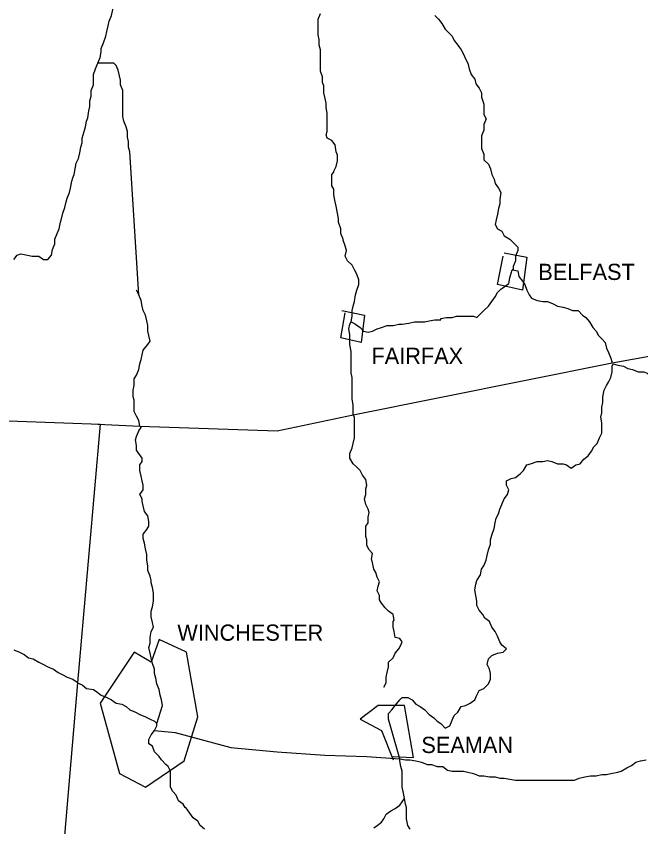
# Model space of a CAD drawing. Extents: x 0 to 34, y 0 to 22.
# Drawn here: x 3.569 to 4.319, y 17.195 to 18.17 of the extents above; entities that cross this region are included whole.
import ezdxf

# ---------------------------------------------------------------- set-up
doc = ezdxf.new("R2010")
doc.units = 0
doc.layers.add('Default', color=7, linetype='Continuous')

msp = doc.modelspace()

# ---------------------------------------------------------------- linework, layer by layer
at = {"layer": 'Default'}
for points in [[(3.00408, 18.71557), (2.98363, 18.02022), (2.9659, 17.693), (3.31221, 17.68346), (3.514, 17.68482), (3.6258, 17.68073), (3.66943, 17.67937)], [(3.6667, 18.11293), (3.66943, 18.11975), (3.67079, 18.12657), (3.67079, 18.13066), (3.67352, 18.13747), (3.67625, 18.14566), (3.67761, 18.15111), (3.67897, 18.15793), (3.68034, 18.16338), (3.68306, 18.1702), (3.68443, 18.17565), (3.68579, 18.18247), (3.68579, 18.18792)], [(3.94211, 18.04613), (3.94211, 18.05294), (3.94075, 18.05976), (3.94075, 18.06521), (3.93939, 18.07203), (3.93802, 18.07748), (3.93802, 18.08566), (3.93666, 18.08976), (3.93666, 18.09657), (3.93393, 18.10339), (3.93393, 18.11021), (3.93393, 18.11566), (3.93393, 18.12111), (3.93393, 18.12929), (3.93257, 18.13475), (3.93257, 18.14157), (3.93121, 18.14702), (3.93121, 18.15384), (3.93121, 18.16065), (3.93121, 18.16611), (3.93393, 18.17292)], [(4.07164, 18.1702), (4.07573, 18.16611), (4.07982, 18.16065), (4.08391, 18.15384), (4.088, 18.14975), (4.09209, 18.14566), (4.09482, 18.1402), (4.09891, 18.13475), (4.103, 18.12929), (4.10572, 18.12384), (4.10845, 18.11839), (4.11118, 18.11293), (4.11254, 18.10612), (4.11527, 18.0993), (4.11936, 18.09385), (4.12072, 18.08839), (4.12481, 18.08294), (4.12754, 18.07748), (4.12754, 18.07203), (4.13027, 18.06385), (4.13027, 18.05703), (4.13027, 18.05158), (4.13299, 18.04613), (4.13027, 18.03931), (4.13027, 18.03249), (4.12754, 18.02567), (4.12754, 18.02295), (4.12754, 18.02158)], [(3.63807, 17.97932), (3.63943, 17.98614), (3.6408, 17.99295), (3.64352, 17.99841), (3.64489, 18.00522), (3.64625, 18.01204), (3.64762, 18.01749), (3.64762, 18.02295), (3.65034, 18.03113), (3.65171, 18.03658), (3.65307, 18.0434), (3.65443, 18.04749), (3.6558, 18.05567), (3.65716, 18.06112), (3.65716, 18.06794), (3.65852, 18.07339), (3.65852, 18.08021), (3.66125, 18.08703), (3.66125, 18.09385), (3.66125, 18.0993), (3.66398, 18.10612), (3.66534, 18.11021), (3.6667, 18.11293)], [(3.70488, 18.00659), (3.70352, 18.01204), (3.70352, 18.01886), (3.70215, 18.02431), (3.70215, 18.03113), (3.70079, 18.03658), (3.69806, 18.0434), (3.6967, 18.04885), (3.6967, 18.05567), (3.6967, 18.06112), (3.6967, 18.06794), (3.6967, 18.07476), (3.6967, 18.08021), (3.69397, 18.08703), (3.69397, 18.09248), (3.69261, 18.09794), (3.69124, 18.10475), (3.68852, 18.11021), (3.68579, 18.11293), (3.67897, 18.11293), (3.67216, 18.11293), (3.6667, 18.11293)], [(3.95029, 17.98341), (3.95302, 17.98886), (3.95438, 17.99568), (3.95438, 18.0025), (3.95302, 18.00659), (3.95166, 18.01477), (3.94757, 18.02022), (3.94211, 18.02295), (3.94075, 18.02704), (3.94211, 18.03113), (3.94211, 18.03795), (3.94211, 18.04476), (3.94211, 18.04476), (3.94211, 18.04613)], [(4.12754, 18.02158), (4.12754, 18.01477), (4.12754, 18.01068), (4.13027, 18.00386), (4.13027, 17.99704), (4.13572, 17.99159), (4.13845, 17.98614), (4.13981, 17.97932), (4.14254, 17.97386), (4.1439, 17.96841), (4.14799, 17.96296), (4.15072, 17.9575), (4.14935, 17.94932), (4.14935, 17.94387), (4.14799, 17.93842), (4.14663, 17.9316), (4.14526, 17.92478), (4.1439, 17.91933), (4.14663, 17.91387), (4.15208, 17.91115), (4.15481, 17.90569), (4.16162, 17.9016), (4.16572, 17.89751), (4.17117, 17.89206), (4.17117, 17.88797), (4.16844, 17.88115), (4.16844, 17.8757), (4.16572, 17.86888), (4.16572, 17.86479), (4.16435, 17.86479)], [(3.71579, 17.8348), (3.70488, 18.00659)], [(3.9612, 17.9016), (3.95848, 17.90842), (3.95848, 17.91387), (3.95575, 17.92205), (3.95575, 17.92614), (3.95438, 17.93296), (3.95302, 17.94114), (3.95166, 17.9466), (3.95029, 17.95478), (3.95029, 17.96159), (3.94757, 17.96568), (3.94757, 17.97386), (3.94757, 17.97932), (3.95029, 17.98204), (3.95029, 17.98341)], [(3.56581, 17.87706), (3.5699, 17.88252), (3.57399, 17.88388), (3.58217, 17.88252), (3.58762, 17.88115), (3.59581, 17.88115), (3.60126, 17.87706), (3.60671, 17.87706), (3.6108, 17.88252), (3.61217, 17.88933), (3.61489, 17.89615), (3.61489, 17.9016), (3.61762, 17.90842), (3.62035, 17.91387), (3.62171, 17.92205), (3.62307, 17.92614), (3.62444, 17.93296), (3.62716, 17.93978), (3.62853, 17.9466), (3.62989, 17.95069), (3.63262, 17.9575), (3.63398, 17.96296), (3.63534, 17.97114), (3.63671, 17.97523), (3.63807, 17.97932), (3.63807, 17.97932)], [(3.97075, 17.80207), (3.97211, 17.80889), (3.97211, 17.81571), (3.97347, 17.82116), (3.97484, 17.82661), (3.9762, 17.8348), (3.97756, 17.84025), (3.98029, 17.84707), (3.98029, 17.85252), (3.97756, 17.85934), (3.97484, 17.86479), (3.97211, 17.87024), (3.96666, 17.8757), (3.96393, 17.88115), (3.96529, 17.88797), (3.96393, 17.89342), (3.9612, 17.90024), (3.9612, 17.9016), (3.9612, 17.9016)], [(4.15481, 17.88524), (4.18208, 17.87979), (4.17662, 17.84025), (4.14663, 17.84707), (4.15344, 17.88115)], [(4.07846, 17.80616), (4.08527, 17.80753), (4.09209, 17.80753), (4.09754, 17.80889), (4.103, 17.80889), (4.11118, 17.80889), (4.118, 17.80889), (4.12209, 17.80753), (4.12754, 17.81298), (4.13027, 17.81571), (4.13572, 17.82116), (4.13981, 17.82661), (4.1439, 17.83207), (4.14663, 17.83752), (4.15072, 17.84161), (4.15481, 17.84434), (4.16026, 17.84843), (4.16162, 17.85525), (4.16299, 17.8607), (4.16435, 17.86479)], [(4.16435, 17.86479), (4.17117, 17.86343), (4.17253, 17.85661), (4.17662, 17.85116), (4.17935, 17.84707), (4.18208, 17.84025), (4.1848, 17.8348), (4.18753, 17.83071), (4.19435, 17.82798), (4.20116, 17.82661), (4.20662, 17.82661), (4.21343, 17.82389), (4.21889, 17.82116), (4.22571, 17.8198), (4.23116, 17.81843), (4.23661, 17.81571), (4.24343, 17.81571), (4.24888, 17.81025), (4.25297, 17.80753), (4.25706, 17.80207), (4.26115, 17.79526), (4.26524, 17.79117), (4.26797, 17.78571), (4.27206, 17.78162), (4.27615, 17.77753), (4.27752, 17.77071), (4.28024, 17.76526), (4.28297, 17.75844), (4.28433, 17.75299)], [(3.71715, 17.67664), (3.71579, 17.68346), (3.71306, 17.68891), (3.71033, 17.69436), (3.71033, 17.70118), (3.71033, 17.708), (3.70897, 17.71209), (3.70897, 17.72027), (3.71033, 17.72572), (3.71033, 17.7339), (3.71306, 17.73799), (3.71579, 17.74481), (3.71715, 17.75163), (3.71851, 17.75708), (3.71988, 17.76253), (3.72124, 17.76799), (3.72669, 17.7748), (3.72942, 17.7789), (3.72806, 17.78571), (3.72669, 17.79117), (3.72669, 17.79798), (3.72533, 17.80344), (3.72397, 17.81025), (3.72124, 17.81571), (3.71988, 17.82116), (3.71851, 17.82798), (3.71579, 17.8348), (3.71306, 17.84025), (3.71306, 17.84025)], [(3.6667, 17.67937), (3.71715, 17.67664), (3.88212, 17.67118), (3.97347, 17.69027), (4.28433, 17.75299), (4.662, 17.82116), (4.68245, 17.82661)], [(3.95984, 17.81571), (3.98711, 17.81025), (3.98302, 17.77753), (3.95848, 17.78299), (3.96393, 17.81298)], [(3.97347, 17.69027), (3.97347, 17.69709), (3.97347, 17.70254), (3.97211, 17.70936), (3.97211, 17.71618), (3.97211, 17.72163), (3.97211, 17.72845), (3.97211, 17.73527), (3.97075, 17.74072), (3.97075, 17.74754), (3.97075, 17.75435), (3.97075, 17.76117), (3.97075, 17.76662), (3.96938, 17.7748), (3.96938, 17.78026), (3.96938, 17.78708), (3.96802, 17.79389), (3.96938, 17.79935), (3.97075, 17.80207)], [(3.97075, 17.80207), (3.9762, 17.79935), (3.98165, 17.79526), (3.98574, 17.79117), (3.9912, 17.7898), (3.99665, 17.79117), (4.0021, 17.79389), (4.00756, 17.79526), (4.01438, 17.79798), (4.02119, 17.79798), (4.02801, 17.79935), (4.0321, 17.79935), (4.04028, 17.80071), (4.0471, 17.80207), (4.05255, 17.80207), (4.05937, 17.80207), (4.06482, 17.80344), (4.07164, 17.8048), (4.07846, 17.8048), (4.07846, 17.80616)], [(4.15753, 17.40941), (4.15208, 17.4135), (4.14935, 17.41759), (4.14663, 17.42441), (4.1439, 17.42986), (4.13981, 17.43531), (4.13708, 17.44213), (4.13163, 17.44622), (4.1289, 17.45031), (4.12481, 17.45576), (4.12209, 17.46122), (4.12209, 17.46667), (4.12072, 17.47349), (4.11936, 17.48031), (4.12072, 17.48712), (4.12209, 17.49121), (4.12618, 17.49803), (4.12754, 17.50485), (4.13027, 17.50894), (4.13299, 17.51575), (4.13436, 17.52121), (4.13572, 17.52803), (4.13845, 17.53484), (4.13845, 17.5403), (4.13981, 17.54575), (4.14254, 17.55393), (4.1439, 17.56075), (4.14526, 17.5662), (4.14799, 17.57166), (4.14935, 17.57711), (4.15208, 17.58256), (4.15481, 17.58938), (4.1589, 17.59483), (4.16026, 17.60029), (4.15753, 17.60574), (4.15753, 17.61119), (4.16299, 17.61392), (4.16844, 17.61528), (4.1739, 17.61937), (4.17799, 17.62347), (4.18208, 17.63028), (4.18617, 17.63165), (4.19435, 17.63437), (4.20116, 17.63437), (4.20662, 17.63574), (4.21207, 17.63437), (4.21889, 17.63165), (4.22571, 17.63165), (4.2298, 17.63028), (4.23525, 17.62619), (4.2407, 17.63028), (4.24616, 17.63165), (4.25025, 17.6371), (4.2557, 17.64119), (4.25979, 17.64664), (4.26252, 17.6521), (4.26661, 17.65619), (4.26934, 17.663), (4.27206, 17.66846), (4.27206, 17.67528), (4.27206, 17.68073), (4.2707, 17.68755), (4.27206, 17.693), (4.27206, 17.69982), (4.27343, 17.70527), (4.27343, 17.71209), (4.27479, 17.72027), (4.27752, 17.72572), (4.28024, 17.72981), (4.28297, 17.73527), (4.28433, 17.74208), (4.28433, 17.7489), (4.2857, 17.75163)], [(4.2857, 17.75163), (4.29115, 17.75026), (4.29797, 17.7489), (4.30342, 17.74617), (4.30887, 17.74481), (4.31569, 17.74208), (4.32251, 17.74208), (4.3266, 17.74072), (4.33205, 17.73527), (4.33478, 17.72981), (4.34023, 17.72709), (4.34569, 17.72299), (4.35114, 17.72027), (4.35523, 17.71618), (4.35796, 17.71618)], [(3.98983, 17.60574), (3.98847, 17.61256), (3.98438, 17.61801), (3.98165, 17.62347), (3.97756, 17.62756), (3.97347, 17.63165), (3.96938, 17.63846), (3.96938, 17.64392), (3.97211, 17.65073), (3.97347, 17.65619), (3.97484, 17.663), (3.97484, 17.66846), (3.97484, 17.67528), (3.97484, 17.68073), (3.97484, 17.68755), (3.97347, 17.69027)], [(3.66943, 17.67937), (3.64216, 17.36851), (3.58899, 16.7427), (3.54127, 16.15506), (3.53172, 15.98191), (3.53036, 15.95873)], [(3.71988, 17.58938), (3.71715, 17.59483), (3.72124, 17.60029), (3.72124, 17.60574), (3.71988, 17.61119), (3.71851, 17.61665), (3.71715, 17.62347), (3.71715, 17.63028), (3.71988, 17.63437), (3.71988, 17.63846), (3.71579, 17.64392), (3.71306, 17.64801), (3.71306, 17.65346), (3.7117, 17.66028), (3.71306, 17.66437), (3.71579, 17.67118), (3.71851, 17.67528), (3.71715, 17.67664), (3.71715, 17.67664)], [(4.02256, 17.44349), (4.02119, 17.45031), (4.01574, 17.4544), (4.01165, 17.45849), (4.00756, 17.46394), (4.00483, 17.46804), (4.00483, 17.47349), (4.0021, 17.47894), (4.00347, 17.4844), (4.00483, 17.48985), (4.0021, 17.4953), (4.00074, 17.50076), (3.99801, 17.50485), (3.99665, 17.51303), (3.99529, 17.51712), (3.99665, 17.52394), (3.99256, 17.52803), (3.98983, 17.53348), (3.98983, 17.5403), (3.98847, 17.54439), (3.98847, 17.54984), (3.98847, 17.55666), (3.9912, 17.56075), (3.9912, 17.56756), (3.99256, 17.57302), (3.9912, 17.57711), (3.98847, 17.58256), (3.98711, 17.58938), (3.98847, 17.59483), (3.98847, 17.60165), (3.98983, 17.60574), (3.98983, 17.60574), (3.98983, 17.60574)], [(3.73078, 17.49121), (3.72942, 17.49667), (3.72669, 17.50348), (3.72669, 17.50894), (3.72533, 17.51575), (3.72533, 17.52257), (3.72397, 17.52939), (3.7226, 17.53621), (3.72124, 17.54166), (3.72124, 17.54711), (3.72533, 17.55257), (3.72806, 17.55666), (3.72806, 17.56211), (3.72669, 17.56893), (3.7226, 17.57438), (3.72124, 17.5812), (3.71988, 17.58665), (3.71988, 17.58938), (3.71988, 17.58938)], [(3.7376, 17.31942), (3.74442, 17.34124), (3.74305, 17.34805), (3.74169, 17.35351), (3.74033, 17.36033), (3.7376, 17.36714), (3.73624, 17.37396), (3.73487, 17.37941), (3.73487, 17.38487), (3.73215, 17.39168), (3.73078, 17.3985), (3.72942, 17.40395), (3.72806, 17.41077), (3.72942, 17.41623), (3.72942, 17.42304), (3.73078, 17.42986), (3.73351, 17.43531), (3.73215, 17.44077), (3.73078, 17.44758), (3.73078, 17.4544), (3.73215, 17.45985), (3.73351, 17.46667), (3.73351, 17.4694), (3.73351, 17.47622), (3.73215, 17.48303), (3.73078, 17.48849), (3.73078, 17.49121)], [(4.01029, 17.36305), (4.01301, 17.36851), (4.01301, 17.37532), (4.01438, 17.38078), (4.01574, 17.38759), (4.01574, 17.39305), (4.02119, 17.3985), (4.02392, 17.40395), (4.02801, 17.40941), (4.03074, 17.4135), (4.0321, 17.41759), (4.02937, 17.42168), (4.02392, 17.42304), (4.02256, 17.42986), (4.02119, 17.43531), (4.02119, 17.44213), (4.02256, 17.44349)], [(3.69261, 17.25943), (3.72397, 17.24307), (3.77032, 17.27443), (3.78668, 17.3276), (3.77305, 17.40532), (3.74033, 17.42032), (3.73078, 17.39305), (3.71033, 17.40532), (3.66943, 17.34396), (3.69261, 17.25943)], [(4.01574, 17.33169), (4.01983, 17.33578), (4.02392, 17.34124), (4.02937, 17.34805), (4.0321, 17.35078), (4.03892, 17.35078), (4.04437, 17.34805), (4.04846, 17.3426), (4.05391, 17.33987), (4.05937, 17.33578), (4.06482, 17.33033), (4.07028, 17.32624), (4.07437, 17.32215), (4.07846, 17.31942), (4.08391, 17.31397), (4.08936, 17.3167), (4.09209, 17.32351), (4.09482, 17.32897), (4.09891, 17.33306), (4.103, 17.33987), (4.10845, 17.34124), (4.11391, 17.34396), (4.11936, 17.34805), (4.12209, 17.35351), (4.12481, 17.35896), (4.13027, 17.36169), (4.13572, 17.36714), (4.13845, 17.3726), (4.13845, 17.37941), (4.13708, 17.38487), (4.13436, 17.39032), (4.13572, 17.39714), (4.13981, 17.40123), (4.14663, 17.40395), (4.15344, 17.40532), (4.15753, 17.40941), (4.15753, 17.40941)], [(3.56581, 17.40804), (3.57263, 17.40532), (3.57808, 17.40259), (3.58353, 17.3985), (3.58899, 17.39714), (3.59581, 17.39305), (3.60126, 17.39032), (3.60671, 17.38759), (3.61353, 17.38487), (3.61898, 17.38078), (3.62444, 17.37805), (3.62989, 17.37532), (3.63671, 17.3726), (3.6408, 17.36987), (3.64216, 17.36851)], [(3.64216, 17.36851), (3.64762, 17.36578), (3.65307, 17.36169), (3.66125, 17.36033), (3.66534, 17.3576), (3.67079, 17.35351), (3.67761, 17.35078), (3.68306, 17.34805), (3.68852, 17.34396), (3.69533, 17.3426), (3.70079, 17.33987), (3.70488, 17.33578), (3.7117, 17.33306), (3.71715, 17.33033), (3.72397, 17.3276), (3.72942, 17.32488), (3.73487, 17.32215), (3.7376, 17.31942), (3.7376, 17.31942)], [(4.01983, 17.27988), (4.04573, 17.27852), (4.03483, 17.34124), (4.00347, 17.34124), (3.98165, 17.32488), (4.00756, 17.31124), (4.02119, 17.27579)], [(4.02937, 17.27716), (4.01574, 17.32488), (4.01574, 17.33169)], [(3.74033, 17.27988), (3.73487, 17.28534), (3.73215, 17.29215), (3.72806, 17.29488), (3.72806, 17.30033), (3.73078, 17.30579), (3.73487, 17.31124), (3.7376, 17.3167), (3.7376, 17.31942)], [(3.73487, 17.31124), (3.75942, 17.30852), (3.82622, 17.29079), (3.88212, 17.28534), (3.93939, 17.28125), (3.98983, 17.27988), (4.02937, 17.27716)], [(3.77169, 17.21853), (3.76896, 17.22262), (3.76351, 17.22671), (3.76078, 17.23353), (3.75669, 17.23762), (3.75396, 17.24307), (3.75396, 17.25125), (3.75396, 17.25671), (3.75396, 17.26216), (3.75124, 17.26761), (3.74851, 17.27034), (3.74305, 17.27579), (3.74033, 17.27988), (3.74033, 17.27988)], [(4.02937, 17.27716), (4.03619, 17.27579), (4.04164, 17.27579), (4.04846, 17.27443), (4.05528, 17.27307), (4.0621, 17.27034), (4.06755, 17.27034), (4.07437, 17.26761), (4.08118, 17.26761), (4.08664, 17.26352), (4.09209, 17.26216), (4.09754, 17.26216), (4.10572, 17.26216), (4.11118, 17.2608), (4.118, 17.25943), (4.12481, 17.25671), (4.13027, 17.25671), (4.13708, 17.25534), (4.1439, 17.25534), (4.14935, 17.25398), (4.15481, 17.25398), (4.16162, 17.25261), (4.16844, 17.25125), (4.17662, 17.25125), (4.18208, 17.25125), (4.18753, 17.25125), (4.19435, 17.25125), (4.20116, 17.25125), (4.20798, 17.25125), (4.21343, 17.25125), (4.21889, 17.25125), (4.22571, 17.25125), (4.23252, 17.25125), (4.23934, 17.25125), (4.24479, 17.25398), (4.25161, 17.25534), (4.25843, 17.25671), (4.26524, 17.25671), (4.27206, 17.25807), (4.27752, 17.25807), (4.28297, 17.25943), (4.29115, 17.2608), (4.29524, 17.26216), (4.30206, 17.26625), (4.30751, 17.26898), (4.31296, 17.27307), (4.31842, 17.27443), (4.32524, 17.27579)], [(4.03483, 17.22944), (4.03346, 17.23762), (4.0321, 17.24307), (4.0321, 17.24989), (4.0321, 17.25671), (4.0321, 17.26216), (4.03074, 17.26761), (4.02937, 17.27443), (4.02937, 17.27716)], [(3.99801, 17.19399), (4.0021, 17.19671), (4.00756, 17.2008), (4.01029, 17.2049), (4.01301, 17.21035), (4.01847, 17.21444), (4.02392, 17.21717), (4.02937, 17.22126), (4.0321, 17.22535), (4.03483, 17.22944), (4.03483, 17.22944), (4.03483, 17.22944)], [(4.04164, 17.19262), (4.03892, 17.19671), (4.03755, 17.2049), (4.03755, 17.21035), (4.03755, 17.21853), (4.03619, 17.22262), (4.03483, 17.22944), (4.03483, 17.22944)], [(3.79486, 17.19262), (3.78941, 17.19671), (3.78668, 17.20217), (3.78123, 17.20626), (3.77714, 17.21171), (3.77441, 17.2158), (3.77305, 17.21717), (3.77169, 17.21853)]]:
    msp.add_lwpolyline(points, dxfattribs=at)

# ---------------------------------------------------------------- texts
for s, p in [('BELFAST', (4.19571, 17.85252)), ('FAIRFAX', (3.99529, 17.75163)), ('WINCHESTER', (3.76214, 17.41895)), ('SEAMAN', (4.05528, 17.28397))]:
    msp.add_text(s, height=0.019502, dxfattribs=at).set_placement(p)

doc.saveas('drawing.dxf')
